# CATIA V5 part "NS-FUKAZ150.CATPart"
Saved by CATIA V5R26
Part number: NS-FUKAZ150
Bounding box of the stored display mesh (mm): x -99.1 to 99.1, y 0 to 198, z -49.9 to 49.9
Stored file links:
  R:\Document\坂尻\その他\ナベヤデータ変換\安全カバーキャスター\MCBKSAZ150\NS-FUKAZ150.CATPart
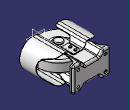
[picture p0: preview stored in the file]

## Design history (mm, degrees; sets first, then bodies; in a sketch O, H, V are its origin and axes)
Body1 (main body)
  Solid1: solid without history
